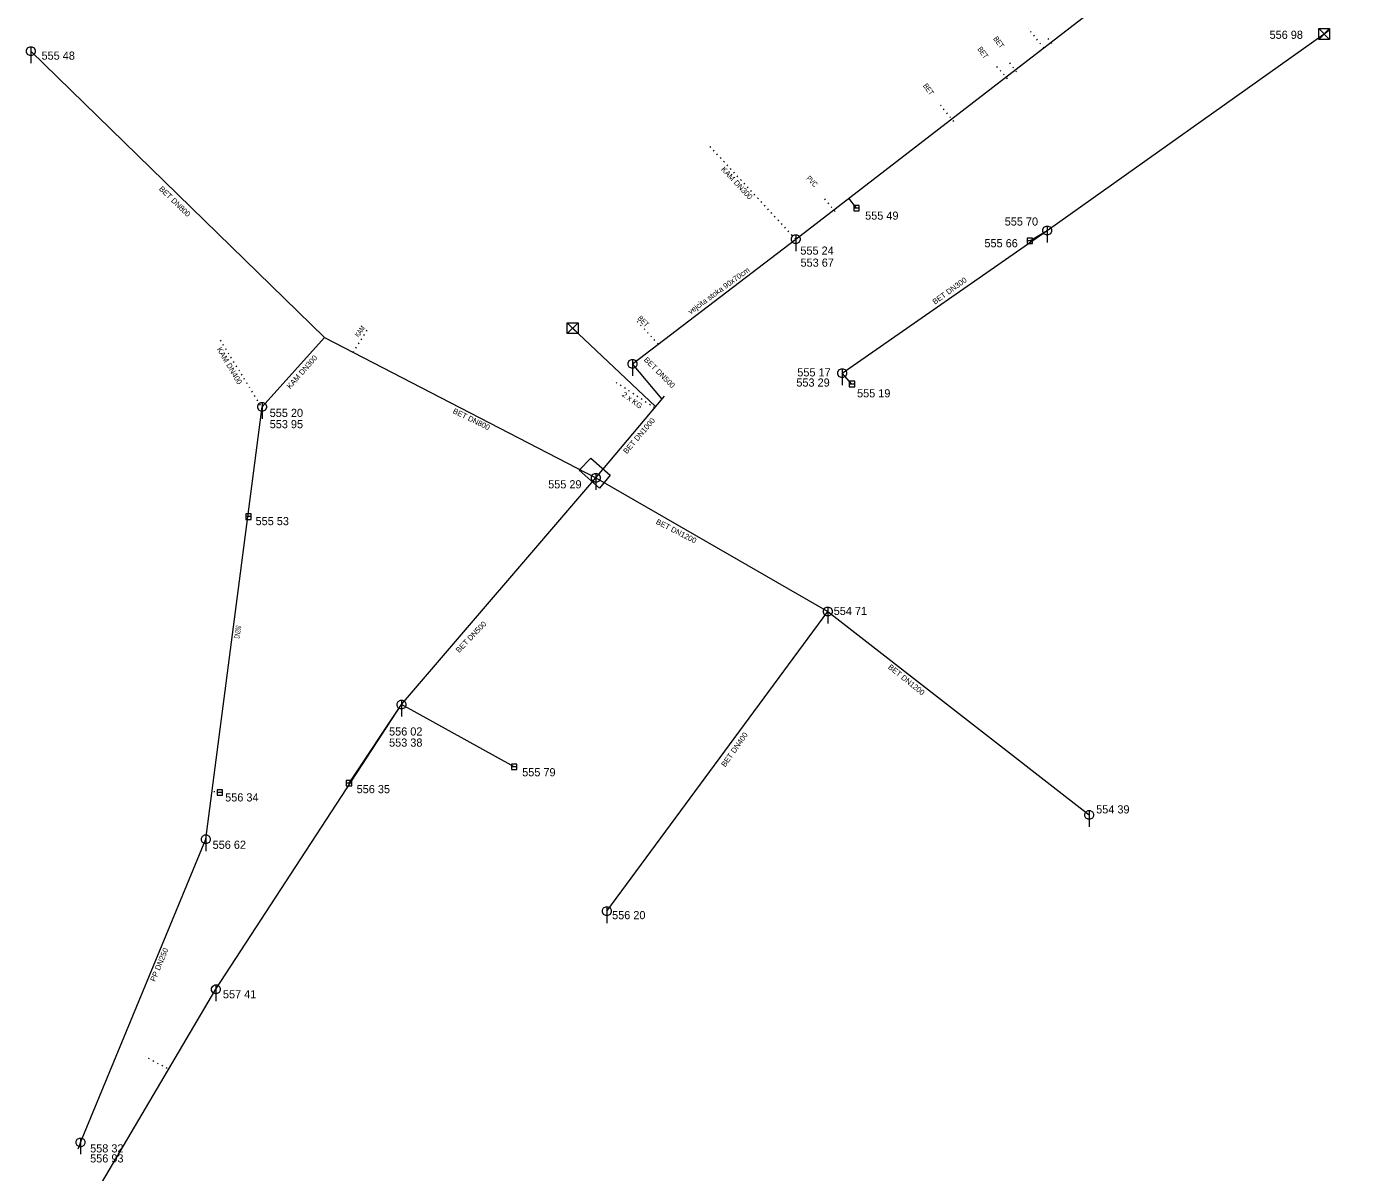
# Model space of a CAD drawing. Extents: x -710806 to -710046, y -1116920 to -1116046.
# Drawn here: x -710472 to -710350.3, y -1116574.5 to -1116469 of the extents above; entities that cross this region are included whole.
import ezdxf
from ezdxf.enums import TextEntityAlignment as Align

# ---------------------------------------------------------------- set-up
doc = ezdxf.new("R2010")
doc.units = 0
doc.header["$LTSCALE"] = 0.3
doc.linetypes.add('DOTTED', pattern=[1.5, 0.3, -1.2])
for name, color, linetype, lineweight in [('40', 7, 'Continuous', 13), ('41', 7, 'Continuous', 13), ('45', 7, 'DOTTED', 13)]:
    doc.layers.add(name, color=color, linetype=linetype, lineweight=lineweight)
doc.layers.add('43', color=7, linetype='Continuous')
doc.layers.add('44', color=7, linetype='Continuous')

msp = doc.modelspace()

# ---------------------------------------------------------------- linework, layer by layer
at = {"layer": '40'}
for p, q in [((-710444.563, -1116497.633), (-710471.573, -1116471.295)), ((-710416.216, -1116500.068), (-710401.2, -1116488.589)), ((-710421.722, -1116496.781), (-710414.085, -1116503.985)), ((-710450.296, -1116504.021), (-710444.563, -1116497.633)), ((-710444.563, -1116497.633), (-710419.591, -1116510.546)), ((-710413.494, -1116503.32), (-710416.216, -1116500.068)), ((-710419.591, -1116510.546), (-710413.273, -1116503.047)), ((-710418.577, -1116550.402), (-710398.25, -1116522.847)), ((-710468.921, -1116581.933), (-710454.536, -1116557.596)), ((-710466.997, -1116571.678), (-710467.241, -1116572.309))]:
    msp.add_line(p, q, dxfattribs=at)
at = {"layer": '40', "linetype": 'DOTTED'}
for p, q in [((-710401.2, -1116488.589), (-710409.306, -1116479.824)), ((-710450.447, -1116503.848), (-710454.199, -1116497.77))]:
    msp.add_line(p, q, dxfattribs=at)
at = {"layer": '40'}
for points in [[(-710401.2, -1116488.589), (-710372.719, -1116466.635), (-710356.594, -1116453.887), (-710350.334, -1116449.934)], [(-710396.928, -1116500.912), (-710378.062, -1116487.8), (-710352.581, -1116469.715), (-710352.049, -1116469.302)], [(-710466.997, -1116571.678), (-710455.469, -1116543.796), (-710450.296, -1116504.021)], [(-710454.536, -1116557.596), (-710437.461, -1116531.408), (-710419.591, -1116510.546)], [(-710419.591, -1116510.546), (-710398.25, -1116522.847), (-710374.198, -1116541.558)]]:
    msp.add_lwpolyline(points, dxfattribs=at)
at = {"layer": '41'}
for p, q in [((-710353.081, -1116469.215), (-710352.081, -1116470.215)), ((-710352.081, -1116469.215), (-710353.081, -1116470.215)), ((-710471.573, -1116470.895), (-710471.573, -1116472.395)), ((-710395.346, -1116485.484), (-710395.846, -1116485.484)), ((-710395.846, -1116485.484), (-710395.846, -1116485.984)), ((-710395.346, -1116485.734), (-710395.846, -1116485.734)), ((-710395.846, -1116485.984), (-710395.346, -1116485.984)), ((-710395.346, -1116485.984), (-710395.346, -1116485.484)), ((-710378.062, -1116487.4), (-710378.062, -1116488.9)), ((-710401.2, -1116488.189), (-710401.2, -1116489.689)), ((-710379.416, -1116488.501), (-710379.916, -1116488.501)), ((-710379.916, -1116488.501), (-710379.916, -1116489.001)), ((-710379.416, -1116488.751), (-710379.916, -1116488.751)), ((-710379.916, -1116489.001), (-710379.416, -1116489.001)), ((-710379.416, -1116489.001), (-710379.416, -1116488.501)), ((-710422.222, -1116496.281), (-710421.222, -1116497.281)), ((-710421.222, -1116496.281), (-710422.222, -1116497.281)), ((-710416.216, -1116499.668), (-710416.216, -1116501.168)), ((-710396.928, -1116500.512), (-710396.928, -1116502.012)), ((-710395.772, -1116501.67), (-710396.272, -1116501.67)), ((-710396.272, -1116501.67), (-710396.272, -1116502.17)), ((-710395.772, -1116501.92), (-710396.272, -1116501.92)), ((-710396.272, -1116502.17), (-710395.772, -1116502.17)), ((-710395.772, -1116502.17), (-710395.772, -1116501.67)), ((-710450.296, -1116503.621), (-710450.296, -1116505.121)), ((-710419.591, -1116510.146), (-710419.591, -1116511.646)), ((-710451.301, -1116513.866), (-710451.801, -1116513.866)), ((-710451.801, -1116513.866), (-710451.801, -1116514.366)), ((-710451.301, -1116514.116), (-710451.801, -1116514.116)), ((-710451.801, -1116514.366), (-710451.301, -1116514.366)), ((-710451.301, -1116514.366), (-710451.301, -1116513.866)), ((-710398.25, -1116522.447), (-710398.25, -1116523.947)), ((-710437.461, -1116531.008), (-710437.461, -1116532.508)), ((-710426.849, -1116536.873), (-710427.349, -1116536.873)), ((-710427.349, -1116536.873), (-710427.349, -1116537.373)), ((-710426.849, -1116537.123), (-710427.349, -1116537.123)), ((-710427.349, -1116537.373), (-710426.849, -1116537.373)), ((-710426.849, -1116537.373), (-710426.849, -1116536.873)), ((-710442.045, -1116538.382), (-710442.545, -1116538.382)), ((-710442.545, -1116538.382), (-710442.545, -1116538.882)), ((-710442.045, -1116538.632), (-710442.545, -1116538.632)), ((-710442.545, -1116538.882), (-710442.045, -1116538.882)), ((-710442.045, -1116538.882), (-710442.045, -1116538.382)), ((-710453.926, -1116539.246), (-710454.426, -1116539.246)), ((-710454.426, -1116539.246), (-710454.426, -1116539.746)), ((-710453.926, -1116539.496), (-710454.426, -1116539.496)), ((-710454.426, -1116539.746), (-710453.926, -1116539.746)), ((-710453.926, -1116539.746), (-710453.926, -1116539.246)), ((-710374.198, -1116541.158), (-710374.198, -1116542.658)), ((-710455.469, -1116543.396), (-710455.469, -1116544.896)), ((-710418.577, -1116550.002), (-710418.577, -1116551.502)), ((-710454.536, -1116557.196), (-710454.536, -1116558.696)), ((-710466.997, -1116571.278), (-710466.997, -1116572.778))]:
    msp.add_line(p, q, dxfattribs=at)
for points in [[(-710353.081, -1116469.215), (-710352.081, -1116469.215), (-710352.081, -1116470.215), (-710353.081, -1116470.215)], [(-710471.973, -1116471.395), (-710471.973, -1116471.195), (-710471.873, -1116470.995), (-710471.673, -1116470.895), (-710471.473, -1116470.895), (-710471.273, -1116470.995), (-710471.173, -1116471.195), (-710471.173, -1116471.395), (-710471.273, -1116471.595), (-710471.473, -1116471.695), (-710471.673, -1116471.695), (-710471.873, -1116471.595)], [(-710378.462, -1116487.9), (-710378.462, -1116487.7), (-710378.362, -1116487.5), (-710378.162, -1116487.4), (-710377.962, -1116487.4), (-710377.762, -1116487.5), (-710377.662, -1116487.7), (-710377.662, -1116487.9), (-710377.762, -1116488.1), (-710377.962, -1116488.2), (-710378.162, -1116488.2), (-710378.362, -1116488.1)], [(-710401.6, -1116488.689), (-710401.6, -1116488.489), (-710401.5, -1116488.289), (-710401.3, -1116488.189), (-710401.1, -1116488.189), (-710400.9, -1116488.289), (-710400.8, -1116488.489), (-710400.8, -1116488.689), (-710400.9, -1116488.889), (-710401.1, -1116488.989), (-710401.3, -1116488.989), (-710401.5, -1116488.889)], [(-710422.222, -1116496.281), (-710421.222, -1116496.281), (-710421.222, -1116497.281), (-710422.222, -1116497.281)], [(-710416.616, -1116500.168), (-710416.616, -1116499.968), (-710416.516, -1116499.768), (-710416.316, -1116499.668), (-710416.116, -1116499.668), (-710415.916, -1116499.768), (-710415.816, -1116499.968), (-710415.816, -1116500.168), (-710415.916, -1116500.368), (-710416.116, -1116500.468), (-710416.316, -1116500.468), (-710416.516, -1116500.368)], [(-710397.328, -1116501.012), (-710397.328, -1116500.812), (-710397.228, -1116500.612), (-710397.028, -1116500.512), (-710396.828, -1116500.512), (-710396.628, -1116500.612), (-710396.528, -1116500.812), (-710396.528, -1116501.012), (-710396.628, -1116501.212), (-710396.828, -1116501.312), (-710397.028, -1116501.312), (-710397.228, -1116501.212)], [(-710450.696, -1116504.121), (-710450.696, -1116503.921), (-710450.596, -1116503.721), (-710450.396, -1116503.621), (-710450.196, -1116503.621), (-710449.996, -1116503.721), (-710449.896, -1116503.921), (-710449.896, -1116504.121), (-710449.996, -1116504.321), (-710450.196, -1116504.421), (-710450.396, -1116504.421), (-710450.596, -1116504.321)], [(-710420.036, -1116508.736), (-710418.278, -1116510.292), (-710419.264, -1116511.497), (-710421.123, -1116509.844)], [(-710419.991, -1116510.646), (-710419.991, -1116510.446), (-710419.891, -1116510.246), (-710419.691, -1116510.146), (-710419.491, -1116510.146), (-710419.291, -1116510.246), (-710419.191, -1116510.446), (-710419.191, -1116510.646), (-710419.291, -1116510.846), (-710419.491, -1116510.946), (-710419.691, -1116510.946), (-710419.891, -1116510.846)], [(-710398.65, -1116522.947), (-710398.65, -1116522.747), (-710398.55, -1116522.547), (-710398.35, -1116522.447), (-710398.15, -1116522.447), (-710397.95, -1116522.547), (-710397.85, -1116522.747), (-710397.85, -1116522.947), (-710397.95, -1116523.147), (-710398.15, -1116523.247), (-710398.35, -1116523.247), (-710398.55, -1116523.147)], [(-710437.861, -1116531.508), (-710437.861, -1116531.308), (-710437.761, -1116531.108), (-710437.561, -1116531.008), (-710437.361, -1116531.008), (-710437.161, -1116531.108), (-710437.061, -1116531.308), (-710437.061, -1116531.508), (-710437.161, -1116531.708), (-710437.361, -1116531.808), (-710437.561, -1116531.808), (-710437.761, -1116531.708)], [(-710374.598, -1116541.658), (-710374.598, -1116541.458), (-710374.498, -1116541.258), (-710374.298, -1116541.158), (-710374.098, -1116541.158), (-710373.898, -1116541.258), (-710373.798, -1116541.458), (-710373.798, -1116541.658), (-710373.898, -1116541.858), (-710374.098, -1116541.958), (-710374.298, -1116541.958), (-710374.498, -1116541.858)], [(-710455.869, -1116543.896), (-710455.869, -1116543.696), (-710455.769, -1116543.496), (-710455.569, -1116543.396), (-710455.369, -1116543.396), (-710455.169, -1116543.496), (-710455.069, -1116543.696), (-710455.069, -1116543.896), (-710455.169, -1116544.096), (-710455.369, -1116544.196), (-710455.569, -1116544.196), (-710455.769, -1116544.096)], [(-710418.977, -1116550.502), (-710418.977, -1116550.302), (-710418.877, -1116550.102), (-710418.677, -1116550.002), (-710418.477, -1116550.002), (-710418.277, -1116550.102), (-710418.177, -1116550.302), (-710418.177, -1116550.502), (-710418.277, -1116550.702), (-710418.477, -1116550.802), (-710418.677, -1116550.802), (-710418.877, -1116550.702)], [(-710454.936, -1116557.696), (-710454.936, -1116557.496), (-710454.836, -1116557.296), (-710454.636, -1116557.196), (-710454.436, -1116557.196), (-710454.236, -1116557.296), (-710454.136, -1116557.496), (-710454.136, -1116557.696), (-710454.236, -1116557.896), (-710454.436, -1116557.996), (-710454.636, -1116557.996), (-710454.836, -1116557.896)], [(-710467.397, -1116571.778), (-710467.397, -1116571.578), (-710467.297, -1116571.378), (-710467.097, -1116571.278), (-710466.897, -1116571.278), (-710466.697, -1116571.378), (-710466.597, -1116571.578), (-710466.597, -1116571.778), (-710466.697, -1116571.978), (-710466.897, -1116572.078), (-710467.097, -1116572.078), (-710467.297, -1116571.978)]]:
    msp.add_lwpolyline(points, close=True, dxfattribs=at)
at = {"layer": '45'}
for p, q in [((-710378.376, -1116470.994), (-710379.825, -1116469.174)), ((-710377.635, -1116470.591), (-710377.993, -1116470.098)), ((-710381.721, -1116473.834), (-710382.76, -1116472.641)), ((-710380.891, -1116473.208), (-710381.679, -1116472.125)), ((-710386.657, -1116477.76), (-710387.971, -1116476.156)), ((-710397.583, -1116486.044), (-710398.708, -1116484.656)), ((-710413.832, -1116498.246), (-710415.808, -1116496.128)), ((-710441.898, -1116499.01), (-710440.55, -1116496.841)), ((-710414.185, -1116504.11), (-710418.028, -1116501.575)), ((-710454.176, -1116539.496), (-710454.897, -1116539.402)), ((-710459.034, -1116564.885), (-710461.055, -1116563.784))]:
    msp.add_line(p, q, dxfattribs=at)
at = {"layer": '45', "linetype": 'Continuous'}
for p, q in [((-710395.596, -1116485.734), (-710396.304, -1116484.815)), ((-710379.666, -1116488.751), (-710378.062, -1116487.8)), ((-710396.022, -1116501.92), (-710396.928, -1116500.912)), ((-710442.295, -1116538.632), (-710437.461, -1116531.408)), ((-710427.099, -1116537.123), (-710437.461, -1116531.408))]:
    msp.add_line(p, q, dxfattribs=at)

# ---------------------------------------------------------------- texts
at = {"layer": '43'}
for s, p in [('556 98 ', (-710355.9282, -1116470.165)), ('555 48 ', (-710468.9112, -1116472.084)), ('555 49 ', (-710393.1362, -1116486.8)), ('555 70 ', (-710380.2962, -1116487.343)), ('555 66 ', (-710382.1592, -1116489.338)), ('555 24 ', (-710399.0952, -1116490.017)), ('555 17 ', (-710399.3792, -1116501.219)), ('555 19 ', (-710393.8802, -1116503.144)), ('555 20 ', (-710447.9192, -1116504.95)), ('555 29 ', (-710422.2982, -1116511.518)), ('555 53 ', (-710449.2172, -1116514.902)), ('554 71 ', (-710396.0282, -1116523.167)), ('556 02 ', (-710436.9372, -1116534.254)), ('555 79 ', (-710424.6872, -1116538.005)), ('556 35 ', (-710439.9182, -1116539.558)), ('556 34 ', (-710452.0162, -1116540.319)), ('554 39 ', (-710371.8802, -1116541.419)), ('556 62 ', (-710453.1702, -1116544.676)), ('556 20 ', (-710416.4172, -1116551.152)), ('557 41 ', (-710452.2212, -1116558.429)), ('558 32 ', (-710464.4392, -1116572.607))]:
    msp.add_text(s, height=0.75, dxfattribs=at).set_placement(p, align=Align.CENTER)
for s, p in [('553 67', (-710400.755, -1116491.126)), ('553 29', (-710401.137, -1116502.155)), ('553 95', (-710449.59, -1116505.982)), ('553 38', (-710438.609, -1116535.277)), ('556 93', (-710466.112, -1116573.527))]:
    msp.add_text(s, height=0.75, dxfattribs=at).set_placement(p)
at = {"layer": '44'}
for s, rotation, width, p in [('BET', 306, 0.7, (-710384.507, -1116471.119)), ('BET', 306, 0.7, (-710383.049, -1116470.162)), ('BET', 306, 0.7, (-710389.518, -1116474.491)), ('PVC', 315, 0.65, (-710400.271, -1116483.056)), ('BET', 315, 0.7, (-710415.787, -1116495.921)), ('KAM', 54, 0.6, (-710441.407, -1116497.659)), ('DN200', 81, 0.45, (-710452.384, -1116525.349))]:
    msp.add_text(s, height=0.5, rotation=rotation, dxfattribs=dict(at, width=width)).set_placement(p)
for s, rotation, p in [('KAM DN300', 313.2, (-710408.102, -1116482.201)), ('BET DN800', 315.9, (-710459.815, -1116484.019)), ('vejcita stoka 90x70cm', 36, (-710410.873, -1116495.526)), ('BET DN300', 36, (-710388.386, -1116494.627)), ('KAM DN400', 300.6, (-710454.476, -1116498.713)), ('KAM DN300', 48.6, (-710447.702, -1116502.412)), ('BET DN500', 315, (-710415.204, -1116499.736)), ('2 x KG', 324, (-710417.23, -1116502.989)), ('BET DN800', 333.9, (-710432.794, -1116504.567)), ('BET DN1000', 49.5, (-710416.741, -1116508.384)), ('BET DN1200', 333, (-710414.11, -1116514.751)), ('BET DN500', 45.9, (-710432.171, -1116526.678)), ('BET DN1200', 321.3, (-710392.754, -1116528.045)), ('BET DN400', 54.9, (-710407.688, -1116537.195)), ('PP DN250', 67.5, (-710460.145, -1116556.933))]:
    msp.add_text(s, height=0.5, rotation=rotation, dxfattribs=at).set_placement(p)

doc.saveas('drawing.dxf')
